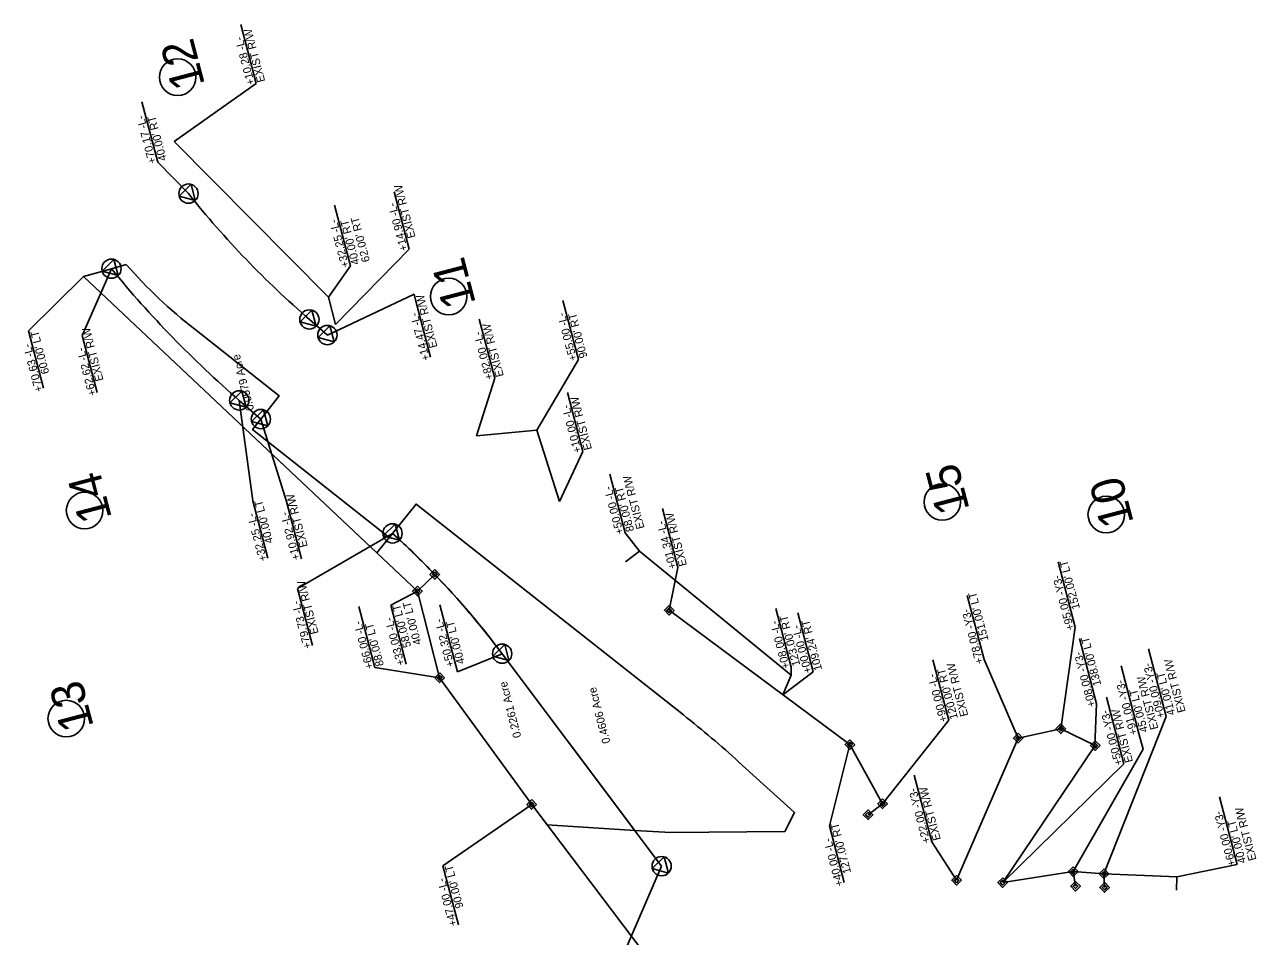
# Model space of a CAD drawing. Extents: x 1366833 to 1368739, y 877580 to 880469.
# Drawn here: x 1366833 to 1367753, y 879788 to 880469 of the extents above; entities that cross this region are included whole.
import ezdxf

# ---------------------------------------------------------------- set-up
doc = ezdxf.new("R2010")
doc.units = 0
for name, color, linetype in [('Exist Hydro Jurisdictional Stream or Body of Water', 7, 'Continuous'), ('Exist Hydrographic River Shore', 7, 'Continuous'), ('Exist Road Primary NC Attributed', 7, 'Continuous'), ('Exist Road Primary US Divided Attributed', 7, 'Continuous'), ('Exist Structure Major Deck Tunnel Box Culvert', 7, 'Continuous'), ('P_RDY_Profile_Special_Ditch_L', 7, 'Continuous'), ('Prop Horizontal Alignment Station Label', 7, 'Continuous'), ('Prop North Arrow for Plan Sheets CELL', 7, 'Continuous'), ('Prop Shade Medium', 7, 'Continuous'), ('Scratch_Level_0', 7, 'Continuous'), ('Scratch_Level_3', 7, 'Continuous'), ('Sheet Clip Boundary CELL', 7, 'Continuous'), ('Sheet Professional Seal CELL', 7, 'Continuous'), ('Sheet Title Data Points CELL', 7, 'Continuous')]:
    doc.layers.add(name, color=color, linetype=linetype)

msp = doc.modelspace()

# ---------------------------------------------------------------- linework, layer by layer
at = {"layer": 'Exist Hydro Jurisdictional Stream or Body of Water'}
for p, q in [((1367618.12, 880019.04), (1367605.33, 880067.83)), ((1367549.93, 879994.94), (1367537.42, 880042.67)), ((1367634.08, 879961.73), (1367621.27, 880010.61)), ((1367641.41, 879966.66), (1367654.45, 879916.89)), ((1367497.82, 879908.46), (1367510.87, 879858.7))]:
    msp.add_line(p, q, dxfattribs=at)
for points in [[(1367618.12, 880019.04), (1367607.31, 879943.16)], [(1367549.93, 879994.94), (1367575.46, 879936.16)], [(1367634.08, 879961.73), (1367632.82, 879930.54)], [(1367654.45, 879916.89), (1367563.88, 879828.18)], [(1367510.87, 879858.7), (1367529.42, 879829.93)]]:
    msp.add_lwpolyline(points, dxfattribs=at)
at = {"layer": 'Exist Hydrographic River Shore'}
for p, q in [((1367059.34, 880237.31), (1367045.9, 880248.95)), ((1367009.67, 880174.5), (1366993.54, 880188.46)), ((1367309.09, 879840.47), (1367189.94, 879999.22))]:
    msp.add_line(p, q, dxfattribs=at)
for centre, radius, start, end in [((1367510.59, 880785.76), 710, 218.58264, 229.11901), ((1367510.59, 880785.76), 790, 219.15968, 229.11901), ((1366677.28, 879614.42), 641, 36.89155, 47.77917)]:
    msp.add_arc(centre, radius, start, end, dxfattribs=at)
at = {"layer": 'Exist Road Primary NC Attributed'}
for p, q in [((1367607.31, 879943.16), (1367575.46, 879936.16)), ((1367633, 879930.55), (1367607.31, 879943.16)), ((1367529.42, 879829.93), (1367575.46, 879936.16)), ((1367563.88, 879828.18), (1367633, 879930.55))]:
    msp.add_line(p, q, dxfattribs=at)
at = {"layer": 'Exist Road Primary US Divided Attributed'}
msp.add_line((1366898.03, 880286.89), (1366908.95, 880289.96), dxfattribs=at)
for points in [[(1366993.54, 880188.46), (1367009.67, 880174.5), (1367003.48, 880166.68), (1367105.58, 880086.08), (1367096.3, 880074.53), (1366877.09, 880281), (1366898.03, 880286.89)], [(1366960.2, 880241.59), (1367023.33, 880191.77), (1367009.67, 880174.5), (1366993.54, 880188.46)], [(1367108.03, 880089.12), (1367125.63, 880111.02), (1367325.3, 879953.41)], [(1367139.57, 880058.47), (1367126.58, 880046), (1367096.3, 880074.53), (1367108.03, 880089.12)], [(1367189.94, 879999.22), (1367289.01, 879867.23), (1367223.47, 879871.39), (1367211.98, 879886.57), (1367143.23, 879981.23), (1367126.58, 880046), (1367139.57, 880058.47)], [(1367366.83, 879918.28), (1367408.46, 879880.56), (1367401.07, 879866.44), (1367315.88, 879865.52), (1367289.01, 879867.23), (1367189.94, 879999.22)]]:
    msp.add_lwpolyline(points, dxfattribs=at)
for centre, radius, start, end in [((1367208.01, 880555.55), 399.97, 221.60674, 231.71513), ((1367510.59, 880785.76), 790, 219.15968, 229.11901), ((1367510.59, 880785.76), 790, 219.15968, 229.11901), ((1366677.28, 879614.42), 641, 36.89155, 47.77917), ((1366677.28, 879614.42), 641, 43.8475, 47.77917), ((1366677.28, 879614.42), 641, 36.89155, 43.8475), ((1366829.33, 879325.06), 800.51, 47.8212, 51.71513)]:
    msp.add_arc(centre, radius, start, end, dxfattribs=at)
at = {"layer": 'Exist Structure Major Deck Tunnel Box Culvert'}
for p, q in [((1366920.73, 880411.64), (1366932.58, 880366.41)), ((1367124.14, 880267.86), (1367059.34, 880237.31)), ((1367125.55, 880262.49), (1367124.14, 880267.86)), ((1367125.55, 880262.49), (1367136.47, 880220.82)), ((1366876.21, 880237.01), (1366887.39, 880194.37)), ((1367003.64, 880113.32), (1367014.81, 880070.69)), ((1367028.77, 880112.81), (1367039.94, 880070.18)), ((1367036.95, 880047.94), (1367108.03, 880089.12)), ((1367036.94, 880048), (1367048.11, 880005.36)), ((1367143.45, 880035.64), (1367155.28, 879990.48)), ((1367156.51, 879985.78), (1367189.94, 879999.22)), ((1367155.28, 879990.48), (1367156.51, 879985.78)), ((1367280.96, 879775.25), (1367309.09, 879840.47))]:
    msp.add_line(p, q, dxfattribs=at)
for points in [[(1366932.58, 880366.41), (1366955.57, 880342.97)], [(1366876.21, 880237.01), (1366898.03, 880286.89)], [(1367003.64, 880113.32), (1366993.54, 880188.46)], [(1367028.77, 880112.81), (1367009.67, 880174.5)]]:
    msp.add_lwpolyline(points, dxfattribs=at)
at = {"layer": 'P_RDY_Profile_Special_Ditch_L'}
for points in [[(1367139.59, 880062.07), (1367143.16, 880058.45), (1367139.55, 880054.87), (1367135.97, 880058.49)], [(1367139.58, 880060.27), (1367141.37, 880058.46), (1367139.56, 880056.67), (1367137.77, 880058.48)], [(1367126.6, 880049.6), (1367130.18, 880045.98), (1367126.56, 880042.4), (1367122.98, 880046.02)], [(1367126.59, 880047.8), (1367128.38, 880045.99), (1367126.57, 880044.2), (1367124.78, 880046.01)], [(1367314.74, 880035.23), (1367318.32, 880031.61), (1367314.7, 880028.03), (1367311.12, 880031.65)], [(1367314.73, 880033.43), (1367316.52, 880031.62), (1367314.71, 880029.83), (1367312.92, 880031.64)], [(1367143.25, 879984.83), (1367146.83, 879981.21), (1367143.21, 879977.63), (1367139.63, 879981.25)], [(1367143.24, 879983.03), (1367145.03, 879981.22), (1367143.22, 879979.43), (1367141.43, 879981.24)], [(1367575.48, 879939.76), (1367579.06, 879936.14), (1367575.44, 879932.56), (1367571.86, 879936.18)], [(1367607.33, 879946.76), (1367610.91, 879943.14), (1367607.29, 879939.56), (1367603.71, 879943.18)], [(1367607.32, 879944.96), (1367609.11, 879943.15), (1367607.3, 879941.36), (1367605.51, 879943.17)], [(1367449.78, 879934.86), (1367453.36, 879931.24), (1367449.74, 879927.66), (1367446.16, 879931.28)], [(1367449.77, 879933.06), (1367451.56, 879931.25), (1367449.75, 879929.46), (1367447.96, 879931.27)], [(1367575.47, 879937.96), (1367577.26, 879936.15), (1367575.45, 879934.36), (1367573.66, 879936.17)], [(1367633.02, 879934.15), (1367636.6, 879930.53), (1367632.98, 879926.95), (1367629.4, 879930.57)], [(1367633.01, 879932.35), (1367634.8, 879930.54), (1367632.99, 879928.75), (1367631.2, 879930.56)], [(1367212, 879890.17), (1367215.58, 879886.55), (1367211.96, 879882.97), (1367208.38, 879886.59)], [(1367211.99, 879888.37), (1367213.78, 879886.56), (1367211.97, 879884.77), (1367210.18, 879886.58)], [(1367474.2, 879890.67), (1367477.78, 879887.05), (1367474.16, 879883.47), (1367470.58, 879887.09)], [(1367474.19, 879888.87), (1367475.98, 879887.06), (1367474.17, 879885.27), (1367472.38, 879887.08)], [(1367463.31, 879882.5), (1367466.89, 879878.88), (1367463.27, 879875.3), (1367459.69, 879878.92)], [(1367463.3, 879880.7), (1367465.09, 879878.89), (1367463.28, 879877.1), (1367461.49, 879878.91)], [(1367616.61, 879839.98), (1367620.19, 879836.36), (1367616.57, 879832.78), (1367612.99, 879836.4)], [(1367616.6, 879838.18), (1367618.39, 879836.37), (1367616.58, 879834.58), (1367614.79, 879836.39)], [(1367639.58, 879838.36), (1367643.16, 879834.74), (1367639.54, 879831.16), (1367635.96, 879834.78)], [(1367529.44, 879833.53), (1367533.02, 879829.91), (1367529.4, 879826.33), (1367525.82, 879829.95)], [(1367529.43, 879831.73), (1367531.22, 879829.92), (1367529.41, 879828.13), (1367527.62, 879829.94)], [(1367563.9, 879831.78), (1367567.48, 879828.16), (1367563.86, 879824.58), (1367560.28, 879828.2)], [(1367563.89, 879829.98), (1367565.68, 879828.17), (1367563.87, 879826.38), (1367562.08, 879828.19)], [(1367618.35, 879829.08), (1367621.93, 879825.47), (1367618.31, 879821.89), (1367614.73, 879825.5)], [(1367640.08, 879828.14), (1367643.66, 879824.52), (1367640.04, 879820.94), (1367636.46, 879824.56)], [(1367639.57, 879836.56), (1367641.36, 879834.75), (1367639.55, 879832.96), (1367637.76, 879834.77)], [(1367618.34, 879827.29), (1367620.13, 879825.48), (1367618.32, 879823.69), (1367616.53, 879825.5)], [(1367640.07, 879826.34), (1367641.86, 879824.53), (1367640.05, 879822.74), (1367638.26, 879824.55)]]:
    msp.add_lwpolyline(points, close=True, dxfattribs=at)
at = {"layer": 'Prop Horizontal Alignment Station Label'}
for p, q in [((1367094.81, 879988.94), (1367082.89, 880034.4)), ((1367106.65, 880035.48), (1367118.19, 879991.47)), ((1367145.66, 879840.74), (1367157.2, 879796.72))]:
    msp.add_line(p, q, dxfattribs=at)
for points in [[(1367106.65, 880035.48), (1367126.58, 880046)], [(1367094.81, 879988.94), (1367143.23, 879981.23)], [(1367145.66, 879840.74), (1367211.98, 879886.57)]]:
    msp.add_lwpolyline(points, dxfattribs=at)
at = {"layer": 'Prop North Arrow for Plan Sheets CELL'}
for p, q in [((1367126.58, 880046), (1367139.57, 880058.47)), ((1367143.23, 879981.23), (1367126.58, 880046)), ((1367211.98, 879886.57), (1367143.23, 879981.23)), ((1367371.42, 879676.02), (1367211.98, 879886.57))]:
    msp.add_line(p, q, dxfattribs=at)
at = {"layer": 'Prop Shade Medium'}
for p, q in [((1367449.76, 879931.26), (1367314.72, 880031.63)), ((1367474.18, 879887.07), (1367449.76, 879931.26)), ((1367463.29, 879878.9), (1367474.18, 879887.07))]:
    msp.add_line(p, q, dxfattribs=at)
msp.add_lwpolyline([(1367640.06, 879824.54), (1367639.56, 879834.76), (1367616.59, 879836.38), (1367618.33, 879825.49)], dxfattribs=at)
at = {"layer": 'Scratch_Level_0'}
for p, q in [((1366994.61, 880469.23), (1367006.15, 880425.21)), ((1367120.39, 880301.48), (1367109.14, 880344.39)), ((1367076.66, 880288.99), (1367064.75, 880334.44)), ((1367076.66, 880288.99), (1367060.3, 880265.58)), ((1367235.38, 880263.17), (1367246.91, 880219.15)), ((1367172.86, 880249.07), (1367184.4, 880205.05)), ((1366847.37, 880197.54), (1366836.12, 880240.46)), ((1367246.91, 880219.15), (1367215.78, 880166.21)), ((1367184.4, 880205.05), (1367170.83, 880161.99)), ((1367238.74, 880194.43), (1367250.28, 880150.41)), ((1367250.28, 880150.41), (1367232.76, 880113.04)), ((1367270.27, 880133.43), (1367281.8, 880089.41)), ((1367394.4, 880033.1), (1367405.93, 879989.08)), ((1367410.77, 880029.65), (1367422.31, 879985.64)), ((1367739.04, 879841.73), (1367725.81, 879892.19))]:
    msp.add_line(p, q, dxfattribs=at)
for points in [[(1367006.15, 880425.21), (1366944.9, 880381.98)], [(1367120.39, 880301.48), (1367065.48, 880245.06)], [(1366836.12, 880240.46), (1366877.09, 880281)], [(1367281.8, 880089.41), (1367292.5, 880075.8)], [(1367422.31, 879985.64), (1367399.54, 879968.58)], [(1367405.93, 879989.08), (1367405.74, 879983.24)], [(1367739.04, 879841.73), (1367694.08, 879832.46)]]:
    msp.add_lwpolyline(points, dxfattribs=at)
at = {"layer": 'Scratch_Level_3'}
for p, q in [((1366955.57, 880342.97), (1366955.57, 880342.97)), ((1366898.03, 880286.89), (1366898.03, 880286.89)), ((1367045.9, 880248.95), (1367045.9, 880248.95)), ((1367059.34, 880237.31), (1367059.34, 880237.31)), ((1366993.54, 880188.46), (1366993.54, 880188.46)), ((1367009.67, 880174.5), (1367009.67, 880174.5)), ((1367108.03, 880089.12), (1367108.03, 880089.12)), ((1367139.57, 880058.47), (1367139.57, 880058.47)), ((1367126.58, 880046), (1367126.58, 880046)), ((1367314.72, 880031.63), (1367314.72, 880031.63)), ((1367189.94, 879999.22), (1367189.94, 879999.22)), ((1367143.23, 879981.23), (1367143.23, 879981.23)), ((1367607.31, 879943.16), (1367607.31, 879943.16)), ((1367449.76, 879931.26), (1367449.76, 879931.26)), ((1367575.46, 879936.16), (1367575.46, 879936.16)), ((1367633, 879930.55), (1367633, 879930.55)), ((1367211.98, 879886.57), (1367211.98, 879886.57)), ((1367474.18, 879887.07), (1367474.18, 879887.07)), ((1367463.29, 879878.9), (1367463.29, 879878.9)), ((1367309.09, 879840.47), (1367309.09, 879840.47)), ((1367529.42, 879829.93), (1367529.42, 879829.93)), ((1367563.88, 879828.18), (1367563.88, 879828.18)), ((1367616.59, 879836.38), (1367616.59, 879836.38)), ((1367639.56, 879834.76), (1367639.56, 879834.76)), ((1367618.33, 879825.49), (1367618.33, 879825.49)), ((1367640.06, 879824.54), (1367640.06, 879824.54))]:
    msp.add_line(p, q, dxfattribs=at)
for points in [[(1366948.6, 880341.15), (1366957.47, 880349.92), (1366960.65, 880337.86)], [(1366891.05, 880285.06), (1366899.92, 880293.83), (1366903.11, 880281.77)], [(1367038.92, 880247.12), (1367047.79, 880255.9), (1367050.98, 880243.83)], [(1367052.37, 880235.48), (1367061.24, 880244.26), (1367064.42, 880232.19)], [(1366986.56, 880186.64), (1366995.43, 880195.41), (1366998.62, 880183.35)], [(1367002.69, 880172.67), (1367011.56, 880181.45), (1367014.75, 880169.38)], [(1367101.05, 880087.29), (1367109.92, 880096.07), (1367113.11, 880084.01)], [(1367182.96, 879997.39), (1367191.83, 880006.16), (1367195.02, 879994.1)], [(1367302.12, 879838.64), (1367310.99, 879847.42), (1367314.17, 879835.35)]]:
    msp.add_lwpolyline(points, close=True, dxfattribs=at)
for centre in [(1366955.57, 880342.97), (1366898.03, 880286.89), (1367045.9, 880248.95), (1367059.34, 880237.31), (1366993.54, 880188.46), (1367009.67, 880174.5), (1367108.03, 880089.12), (1367189.94, 879999.22), (1367309.09, 879840.47)]:
    msp.add_circle(centre, 7.2, dxfattribs=at)
at = {"layer": 'Sheet Clip Boundary CELL'}
for p, q in [((1367309.72, 880107.62), (1367321.26, 880063.6)), ((1367686.05, 879952.36), (1367672.83, 880002.83)), ((1367523.66, 879949.43), (1367511.78, 879994.73)), ((1367665.68, 879939.63), (1367652.46, 879990.1)), ((1367449.76, 879931.26), (1367434.41, 879870.5)), ((1367434.41, 879870.5), (1367445.5, 879828.16))]:
    msp.add_line(p, q, dxfattribs=at)
for points in [[(1367321.26, 880063.6), (1367314.72, 880031.63)], [(1367523.66, 879949.43), (1367474.14, 879887.04)], [(1367686.05, 879952.36), (1367639.56, 879834.76)], [(1367665.68, 879939.63), (1367668.78, 879927.79), (1367616.59, 879836.38)]]:
    msp.add_lwpolyline(points, dxfattribs=at)
at = {"layer": 'Sheet Professional Seal CELL'}
for p, q in [((1366947.48, 880429.97), (1366947.48, 880429.97)), ((1367149.99, 880266.09), (1367149.99, 880266.09)), ((1366877.98, 880106.2), (1366877.98, 880106.2)), ((1367518.77, 880112.55), (1367518.77, 880112.55)), ((1367641.29, 880103.16), (1367641.29, 880103.16)), ((1366864.28, 879950.72), (1366864.28, 879950.72))]:
    msp.add_line(p, q, dxfattribs=at)
for centre in [(1366947.48, 880429.97), (1367149.99, 880266.09), (1367518.77, 880112.55), (1366877.98, 880106.2), (1367641.29, 880103.16), (1366864.28, 879950.72)]:
    msp.add_circle(centre, 13.67, dxfattribs=at)
at = {"layer": 'Sheet Title Data Points CELL'}
for p, q in [((1367060.3, 880265.58), (1366944.9, 880381.98)), ((1367126.58, 880046), (1366877.09, 880281)), ((1367065.48, 880245.06), (1367060.3, 880265.58)), ((1367232.76, 880113.04), (1367215.78, 880166.21)), ((1367616.59, 879836.38), (1367563.88, 879828.18)), ((1367694.08, 879832.46), (1367639.56, 879834.76)), ((1367693.69, 879822.47), (1367694.08, 879832.46))]:
    msp.add_line(p, q, dxfattribs=at)
for points in [[(1367215.78, 880166.21), (1367170.83, 880161.99)], [(1367399.54, 879968.58), (1367405.74, 879983.24), (1367292.5, 880075.8), (1367282.03, 880067.93)]]:
    msp.add_lwpolyline(points, dxfattribs=at)

# ---------------------------------------------------------------- texts
at = {"layer": 'Exist Hydro Jurisdictional Stream or Body of Water'}
for s, p in [("152.00' LT", (1367621.65, 880033.18)), ('+95.00 -Y3-', (1367617.48, 880017.5)), ("151.00' LT", (1367553.37, 880009.41)), ('+78.00 -Y3-', (1367549.57, 879992.35)), ("138.00' LT", (1367637.58, 879975.96)), ('+08.00 -Y3-', (1367633.42, 879960.29)), ('EXIST R/W', (1367661.22, 879918.67)), ('+50.00 -Y3-', (1367653.48, 879916.64)), ('+22.00 -Y3-', (1367509.9, 879858.45)), ('EXIST R/W', (1367517.64, 879860.47))]:
    msp.add_text(s, height=6, rotation=104.68512, dxfattribs=at).set_placement(p)
at = {"layer": 'Exist Road Primary US Divided Attributed'}
for s, p in [('0.0579 Acre', (1367004.73, 880181.62)), ('0.2261 Acre', (1367204.25, 879937.18)), ('0.4606 Acre', (1367270.86, 879932.88))]:
    msp.add_text(s, height=6, rotation=104.63287, dxfattribs=at).set_placement(p)
at = {"layer": 'Exist Structure Major Deck Tunnel Box Culvert'}
for s, p in [('+70.17 -L-', (1366931.62, 880366.16)), ("40.00' RT", (1366939.36, 880368.19)), ('EXIST R/W', (1367141.63, 880228.46)), ('+14.47 -L-', (1367135.99, 880218.95)), ('EXIST R/W', (1366892.12, 880203.65)), ('+62.62 -L-', (1366886.85, 880192.76)), ('EXIST R/W', (1367044.68, 880079.46)), ("40.00' LT", (1367018.91, 880082.39)), ('+10.92 -L-', (1367039.04, 880069.95)), ('+32.25 -L-', (1367014.27, 880069.07)), ('EXIST R/W', (1367052.85, 880014.64)), ('+79.73 -L-', (1367047.57, 880003.74)), ('+50.32 -L-', (1367154.32, 879990.22)), ("40.00' LT", (1367162.05, 879992.25))]:
    msp.add_text(s, height=6, rotation=104.68512, dxfattribs=at).set_placement(p)
at = {"layer": 'Prop Horizontal Alignment Station Label'}
for s, p in [("58.00' LT", (1367121.99, 880004.57)), ("40.00' LT", (1367129.73, 880006.6)), ('+66.00 -L-', (1367093.87, 879988.55)), ("88.00' LT", (1367101.61, 879990.58)), ('+33.00 -L-', (1367117.22, 879991.21)), ("90.00' LT", (1367161.1, 879809.8)), ('+47.00 -L-', (1367156.33, 879796.44))]:
    msp.add_text(s, height=6, rotation=104.68512, dxfattribs=at).set_placement(p)
at = {"layer": 'Scratch_Level_0'}
for s, height, p in [('EXIST R/W', 6, (1367012.92, 880426.99)), ('12', 25, (1366968.03, 880424.38)), ('+10.28 -L-', 6, (1367005.18, 880424.96)), ('EXIST R/W', 6, (1367125.26, 880310.48)), ('+14.90 -L-', 6, (1367119.49, 880300.94)), ('+32.25 -L-', 6, (1367075.73, 880288.6)), ("40.00' RT", 6, (1367083.47, 880290.62)), ("62.00' RT", 6, (1367091.21, 880292.65)), ('11', 25, (1367170.41, 880260.97)), ('+55.00 -L-', 6, (1367245.95, 880218.9)), ("90.00' RT", 6, (1367253.69, 880220.92)), ('EXIST R/W', 6, (1367191.17, 880206.83)), ("60.00' LT", 6, (1366851.61, 880208.97)), ('+82.00 -L-', 6, (1367183.43, 880204.8)), ('+70.63 -L-', 6, (1366846.84, 880195.62)), ('EXIST R/W', 6, (1367257.05, 880152.19)), ('+10.00 -L-', 6, (1367249.31, 880150.16)), ('14', 25, (1366898.51, 880100.68)), ('15', 25, (1367539.29, 880107.06)), ('+50.00 -L-', 6, (1367280.83, 880089.16)), ("88.00' RT", 6, (1367288.57, 880091.19)), ('EXIST R/W', 6, (1367296.31, 880093.22)), ('10', 25, (1367661.92, 880097.26)), ('+08.00 -L-', 6, (1367404.96, 879988.83)), ("123.00' RT", 6, (1367412.7, 879990.86)), ("109.24' RT", 6, (1367429.08, 879987.41)), ('+00.00 -L-', 6, (1367421.34, 879985.38)), ('13', 25, (1366884.91, 879944.83)), ('EXIST R/W', 6, (1367753.58, 879845.39)), ('+60.00 -Y3-', 6, (1367738.1, 879841.34)), ("40.00' LT", 6, (1367745.84, 879843.36))]:
    msp.add_text(s, height=height, rotation=104.68512, dxfattribs=at).set_placement(p)
at = {"layer": 'Sheet Clip Boundary CELL'}
for s, p in [('+01.34 -L-', (1367320.29, 880063.35)), ('EXIST R/W', (1367328.03, 880065.38)), ('EXIST R/W', (1367700.6, 879956.03)), ("120.00' RT", (1367530.47, 879951.06)), ('EXIST R/W', (1367538.2, 879953.09)), ('+09.00 -Y3-', (1367685.12, 879951.97)), ("41.00' LT", (1367692.86, 879954)), ('+90.00 -L-', (1367522.73, 879949.04)), ('+91.00 -Y3-', (1367664.75, 879939.24)), ('EXIST R/W', (1367680.23, 879943.3)), ("45.00' LT", (1367672.49, 879941.27)), ("127.00' RT", (1367450.76, 879835.7)), ('+40.00 -L-', (1367444.97, 879826.23))]:
    msp.add_text(s, height=6, rotation=104.68512, dxfattribs=at).set_placement(p)

doc.saveas('drawing.dxf')
